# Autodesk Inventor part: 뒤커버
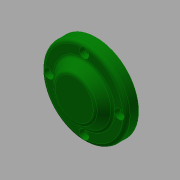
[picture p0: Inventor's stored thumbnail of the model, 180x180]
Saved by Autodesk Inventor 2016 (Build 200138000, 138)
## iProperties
Created: 2017-08
Part Number: 뒤커버
Material: 알루미늄 6061
Document SubType Name: Modeling
Designer: mduedu
Density: 1 g/cm^3
Appearance: 진녹색
Author: mduedu
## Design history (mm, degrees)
sketch "스케치1"
  geometry: C1 r 35 at (0, 0); 1 further point
  constraints: 1 centre point, 1 coincident
  dimensions: "d0" = 70 diameter of C1
extrude "돌출1" new body sketch "스케치1" distance "d1" = 10; taper "d2" = 0 deg
sketch "스케치2"
  geometry: C1 r 24 at (0, 0); 1 further point
  constraints: 1 centre point, 1 coincident
  dimensions: "d3" = 48 diameter of C1
node "작업 평면1"
sketch "스케치3"
  geometry: C1 r 17 at (0, 0); 1 further point
  constraints: 1 centre point, 1 coincident
  dimensions: "d5" = 34 diameter of C1
feature "로프트1" sketch "스케치3" dims "d6" = 0, "d7" = 90 deg, "d8" = 0, "d9" = 90 deg
sketch "스케치4"
  geometry: C1 r 24 at (0, 0) reference; 1 further point
extrude "돌출2" join sketch "스케치4" distance "d10" = 8; taper "d11" = 0 deg
hole "구멍1" diameter "d14" = 40; stored, may be unused: countersink angle "d18" = 90 deg, drill point angle "d20" = 0 deg; dims "d12" = 10, "d13" = 10, "d15" = 6, "d16" = 4, "d17" = 2, "d19" = 12
hole "구멍2" diameter "d23" = 34; stored, may be unused: countersink angle "d27" = 90 deg, drill point angle "d29" = 0 deg; dims "d24" = 6, "d25" = 4, "d26" = 2, "d28" = 6, "d62" = 10, "d63" = 10
chamfer "모따기1" distance "d39" = 1; stored, may be unused: second distance "d40" = 2, angle "d41" = 45 deg
fillet "모깎기1" dims "d42" = 0.3
fillet "모깎기2" dims "d43" = 3
sketch "스케치5" dims "d44" = 58
  geometry: 6 further points
  constraints: 2 vertical alignment, 1 coincident, 7 other
  dimensions: "d47" = 360 deg dimension on point (0, 0) point (0, 29) (derived)
sketch "스케치6" dims "d64" = 58 (derived)
  geometry: 6 further points
  constraints: 1 coincident, 1 vertical alignment, 6 other
hole "구멍4" sketch "스케치6" at (0, 29), (-29, 0), (29, 0), (0, -29) diameter "d49" = 4.5; stored, may be unused: countersink angle "d53" = 90 deg, drill point angle "d55" = 0 deg; dims "d50" = 6, "d51" = 8, "d52" = 4.6, "d54" = 8
fillet "모깎기3" dims "d56" = 3
fillet "모깎기4" dims "d57" = 3
fillet "모깎기5" dims "d58" = 3
node "솔리드1"
other parameters: "d4" = 8
